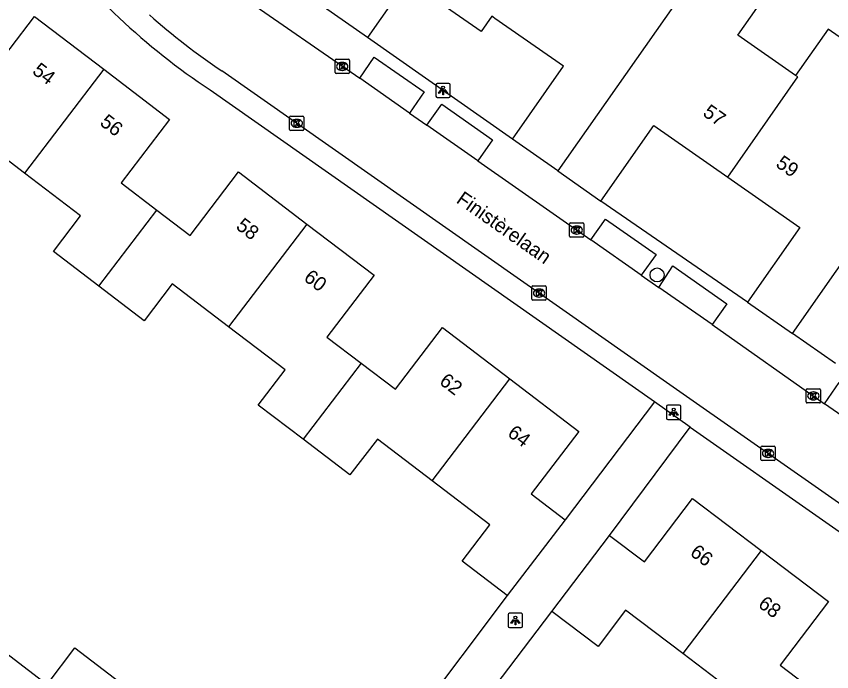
# Model space of a CAD drawing. Extents: x 158474 to 159560, y 388525 to 389605.
# Drawn here: x 158654.3 to 158711.4, y 389093.6 to 389139.5 of the extents above; entities that cross this region are included whole.
import ezdxf

# ---------------------------------------------------------------- set-up
doc = ezdxf.new("R2010")
doc.units = 0
for name, color, linetype in [('IMGEO_Boom', 7, 'Continuous'), ('IMGEO_Kolk', 7, 'Continuous'), ('IMGEO_Lichtpunt', 7, 'Continuous'), ('IMGEO_Openbare_ruimte_label', 7, 'Continuous'), ('IMGEO_Pand', 7, 'Continuous'), ('IMGEO_Pand_nummerreeks', 7, 'Continuous'), ('IMGEO_Rijbaan_lokaal_open', 7, 'Continuous'), ('IMGEO_Voetpad_open', 7, 'Continuous')]:
    doc.layers.add(name, color=color, linetype=linetype)

msp = doc.modelspace()

# ---------------------------------------------------------------- linework, layer by layer
at = {"layer": 'IMGEO_Boom'}
msp.add_circle((158699.155, 389121.384), 0.489, dxfattribs=at)
at = {"layer": 'IMGEO_Kolk'}
for p, q in [((158676.596, 389135.583), (158676.596, 389136.435)), ((158676.671, 389136.509), (158677.523, 389136.509)), ((158677.084, 389136.289), (158677.109, 389136.289)), ((158677.597, 389136.435), (158677.597, 389135.583)), ((158677.107, 389135.729), (158677.082, 389135.729)), ((158677.523, 389135.509), (158676.671, 389135.509)), ((158673.409, 389131.592), (158673.409, 389132.444)), ((158673.484, 389132.518), (158674.336, 389132.518)), ((158673.897, 389132.298), (158673.922, 389132.298)), ((158674.41, 389132.444), (158674.41, 389131.592)), ((158673.92, 389131.738), (158673.895, 389131.738)), ((158674.336, 389131.518), (158673.484, 389131.518)), ((158693.025, 389124.107), (158693.025, 389124.959)), ((158693.1, 389125.033), (158693.952, 389125.033)), ((158693.513, 389124.813), (158693.538, 389124.813)), ((158694.026, 389124.959), (158694.026, 389124.107)), ((158693.536, 389124.253), (158693.511, 389124.253)), ((158693.952, 389124.033), (158693.1, 389124.033)), ((158690.386, 389119.688), (158690.386, 389120.54)), ((158690.461, 389120.614), (158691.313, 389120.614)), ((158690.874, 389120.394), (158690.899, 389120.394)), ((158691.387, 389120.54), (158691.387, 389119.688)), ((158690.897, 389119.834), (158690.872, 389119.834)), ((158691.313, 389119.614), (158690.461, 389119.614)), ((158709.682, 389113.405), (158710.534, 389113.405)), ((158709.607, 389112.479), (158709.607, 389113.331)), ((158710.095, 389113.185), (158710.12, 389113.185)), ((158710.608, 389113.331), (158710.608, 389112.479)), ((158710.534, 389112.405), (158709.682, 389112.405)), ((158710.118, 389112.625), (158710.093, 389112.625)), ((158706.435, 389108.445), (158706.435, 389109.297)), ((158706.51, 389109.371), (158707.362, 389109.371)), ((158706.923, 389109.151), (158706.948, 389109.151)), ((158707.436, 389109.297), (158707.436, 389108.445)), ((158707.362, 389108.371), (158706.51, 389108.371)), ((158706.946, 389108.591), (158706.921, 389108.591))]:
    msp.add_line(p, q, dxfattribs=at)
for points in [[(158676.596, 389135.583), (158676.596, 389136.435)], [(158676.671, 389136.509), (158677.523, 389136.509)], [(158677.597, 389136.435), (158677.597, 389135.583)], [(158676.917, 389136.209), (158677.04, 389136.209), (158677.04, 389136.058), (158677.17, 389136.209), (158677.334, 389136.209), (158677.188, 389136.058), (158677.341, 389135.809), (158677.189, 389135.809), (158677.104, 389135.973), (158677.04, 389135.906), (158677.04, 389135.809), (158676.917, 389135.809), (158676.917, 389136.209)], [(158677.523, 389135.509), (158676.671, 389135.509)], [(158673.409, 389131.592), (158673.409, 389132.444)], [(158673.484, 389132.518), (158674.336, 389132.518)], [(158674.41, 389132.444), (158674.41, 389131.592)], [(158673.73, 389132.218), (158673.853, 389132.218), (158673.853, 389132.067), (158673.983, 389132.218), (158674.147, 389132.218), (158674.001, 389132.067), (158674.154, 389131.818), (158674.002, 389131.818), (158673.917, 389131.982), (158673.853, 389131.915), (158673.853, 389131.818), (158673.73, 389131.818), (158673.73, 389132.218)], [(158674.336, 389131.518), (158673.484, 389131.518)], [(158693.025, 389124.107), (158693.025, 389124.959)], [(158693.1, 389125.033), (158693.952, 389125.033)], [(158694.026, 389124.959), (158694.026, 389124.107)], [(158693.346, 389124.733), (158693.469, 389124.733), (158693.469, 389124.582), (158693.599, 389124.733), (158693.763, 389124.733), (158693.617, 389124.582), (158693.77, 389124.333), (158693.618, 389124.333), (158693.533, 389124.497), (158693.469, 389124.43), (158693.469, 389124.333), (158693.346, 389124.333), (158693.346, 389124.733)], [(158693.952, 389124.033), (158693.1, 389124.033)], [(158690.386, 389119.688), (158690.386, 389120.54)], [(158690.461, 389120.614), (158691.313, 389120.614)], [(158690.707, 389120.314), (158690.83, 389120.314), (158690.83, 389120.163), (158690.96, 389120.314), (158691.124, 389120.314), (158690.978, 389120.163), (158691.131, 389119.914), (158690.979, 389119.914), (158690.894, 389120.078), (158690.83, 389120.011), (158690.83, 389119.914), (158690.707, 389119.914), (158690.707, 389120.314)], [(158691.387, 389120.54), (158691.387, 389119.688)], [(158691.313, 389119.614), (158690.461, 389119.614)], [(158709.682, 389113.405), (158710.534, 389113.405)], [(158709.607, 389112.479), (158709.607, 389113.331)], [(158709.928, 389113.105), (158710.051, 389113.105), (158710.051, 389112.954), (158710.181, 389113.105), (158710.345, 389113.105), (158710.199, 389112.954), (158710.352, 389112.705), (158710.2, 389112.705), (158710.115, 389112.869), (158710.051, 389112.802), (158710.051, 389112.705), (158709.928, 389112.705), (158709.928, 389113.105)], [(158710.608, 389113.331), (158710.608, 389112.479)], [(158710.534, 389112.405), (158709.682, 389112.405)], [(158706.435, 389108.445), (158706.435, 389109.297)], [(158706.51, 389109.371), (158707.362, 389109.371)], [(158706.756, 389109.071), (158706.879, 389109.071), (158706.879, 389108.92), (158707.009, 389109.071), (158707.173, 389109.071), (158707.027, 389108.92), (158707.18, 389108.671), (158707.028, 389108.671), (158706.943, 389108.835), (158706.879, 389108.768), (158706.879, 389108.671), (158706.756, 389108.671), (158706.756, 389109.071)], [(158707.436, 389109.297), (158707.436, 389108.445)], [(158707.362, 389108.371), (158706.51, 389108.371)]]:
    msp.add_lwpolyline(points, dxfattribs=at)
for centre, start, end in [((158676.673, 389136.433), 91.552, 178.448), ((158676.673, 389136.433), 91.552, 178.448), ((158677.521, 389136.433), 1.552, 88.448), ((158677.521, 389136.433), 1.552, 88.448), ((158676.673, 389135.585), 181.552, 268.448), ((158676.673, 389135.585), 181.552, 268.448), ((158677.521, 389135.585), 271.552, 358.448), ((158677.521, 389135.585), 271.552, 358.448), ((158673.486, 389132.442), 91.552, 178.448), ((158673.486, 389132.442), 91.552, 178.448), ((158674.334, 389132.442), 1.552, 88.448), ((158674.334, 389132.442), 1.552, 88.448), ((158673.486, 389131.594), 181.552, 268.448), ((158673.486, 389131.594), 181.552, 268.448), ((158674.334, 389131.594), 271.552, 358.448), ((158674.334, 389131.594), 271.552, 358.448), ((158693.102, 389124.957), 91.552, 178.448), ((158693.102, 389124.957), 91.552, 178.448), ((158693.95, 389124.957), 1.552, 88.448), ((158693.95, 389124.957), 1.552, 88.448), ((158693.102, 389124.109), 181.552, 268.448), ((158693.102, 389124.109), 181.552, 268.448), ((158693.95, 389124.109), 271.552, 358.448), ((158693.95, 389124.109), 271.552, 358.448), ((158690.463, 389120.538), 91.552, 178.448), ((158690.463, 389120.538), 91.552, 178.448), ((158691.311, 389120.538), 1.552, 88.448), ((158691.311, 389120.538), 1.552, 88.448), ((158690.463, 389119.69), 181.552, 268.448), ((158690.463, 389119.69), 181.552, 268.448), ((158691.311, 389119.69), 271.552, 358.448), ((158691.311, 389119.69), 271.552, 358.448), ((158709.684, 389113.329), 91.552, 178.448), ((158709.684, 389113.329), 91.552, 178.448), ((158710.532, 389113.329), 1.552, 88.448), ((158710.532, 389113.329), 1.552, 88.448), ((158709.684, 389112.481), 181.552, 268.448), ((158709.684, 389112.481), 181.552, 268.448), ((158710.532, 389112.481), 271.552, 358.448), ((158710.532, 389112.481), 271.552, 358.448), ((158706.512, 389109.295), 91.552, 178.448), ((158706.512, 389109.295), 91.552, 178.448), ((158707.36, 389109.295), 1.552, 88.448), ((158707.36, 389109.295), 1.552, 88.448), ((158706.512, 389108.447), 181.552, 268.448), ((158706.512, 389108.447), 181.552, 268.448), ((158707.36, 389108.447), 271.552, 358.448), ((158707.36, 389108.447), 271.552, 358.448)]:
    msp.add_arc(centre, 0.0765, start, end, dxfattribs=at)
for centre, major_axis, ratio, start_param, end_param in [((158677.083, 389136.009), (-0.387, 0.002), 0.722429, 4.712389, 7.853982), ((158677.108, 389136.009), (-0.39, 0.002), 0.717154, 1.570796, 4.712389), ((158673.896, 389132.018), (-0.387, 0.002), 0.722429, 4.712389, 7.853982), ((158673.921, 389132.018), (-0.39, 0.002), 0.717154, 1.570796, 4.712389), ((158693.512, 389124.533), (-0.387, 0.002), 0.722429, 4.712389, 7.853982), ((158693.537, 389124.533), (-0.39, 0.002), 0.717154, 1.570796, 4.712389), ((158690.873, 389120.114), (-0.387, 0.002), 0.722429, 4.712389, 7.853982), ((158690.898, 389120.114), (-0.39, 0.002), 0.717154, 1.570796, 4.712389), ((158710.094, 389112.905), (-0.387, 0.002), 0.722429, 4.712389, 7.853982), ((158710.119, 389112.905), (-0.39, 0.002), 0.717154, 1.570796, 4.712389), ((158706.922, 389108.871), (-0.387, 0.002), 0.722429, 4.712389, 7.853982), ((158706.947, 389108.871), (-0.39, 0.002), 0.717154, 1.570796, 4.712389)]:
    msp.add_ellipse(centre, major_axis=major_axis, ratio=ratio, start_param=start_param, end_param=end_param, dxfattribs=at)
at = {"layer": 'IMGEO_Lichtpunt'}
for p, q in [((158683.662, 389134.725), (158683.662, 389133.918)), ((158683.662, 389134.725), (158683.662, 389133.918)), ((158684.564, 389134.82), (158683.756, 389134.82)), ((158684.564, 389134.82), (158683.756, 389134.82)), ((158684.658, 389133.918), (158684.658, 389134.725)), ((158684.658, 389133.918), (158684.658, 389134.725)), ((158683.756, 389133.824), (158684.564, 389133.824)), ((158683.756, 389133.824), (158684.564, 389133.824)), ((158700.726, 389112.25), (158699.918, 389112.25)), ((158700.726, 389112.25), (158699.918, 389112.25)), ((158699.824, 389112.155), (158699.824, 389111.348)), ((158699.824, 389112.155), (158699.824, 389111.348)), ((158700.82, 389111.348), (158700.82, 389112.155)), ((158700.82, 389111.348), (158700.82, 389112.155)), ((158699.918, 389111.254), (158700.726, 389111.254)), ((158699.918, 389111.254), (158700.726, 389111.254)), ((158688.727, 389097.561), (158688.727, 389096.754)), ((158688.727, 389097.561), (158688.727, 389096.754)), ((158689.629, 389097.656), (158688.821, 389097.656)), ((158689.629, 389097.656), (158688.821, 389097.656)), ((158689.723, 389096.754), (158689.723, 389097.561)), ((158689.723, 389096.754), (158689.723, 389097.561)), ((158688.821, 389096.66), (158689.629, 389096.66)), ((158688.821, 389096.66), (158689.629, 389096.66))]:
    msp.add_line(p, q, dxfattribs=at)
for points in [[(158684.036, 389134.389), (158684.075, 389134.361), (158683.887, 389134.099), (158683.849, 389134.126), (158684.036, 389134.389)], [(158684.138, 389134.341), (158684.185, 389134.341), (158684.185, 389134.019), (158684.138, 389134.019), (158684.138, 389134.341)], [(158684.248, 389134.361), (158684.286, 389134.388), (158684.473, 389134.126), (158684.434, 389134.098), (158684.248, 389134.361)], [(158700.198, 389111.819), (158700.237, 389111.791), (158700.049, 389111.529), (158700.011, 389111.556), (158700.198, 389111.819)], [(158700.3, 389111.771), (158700.347, 389111.771), (158700.347, 389111.449), (158700.3, 389111.449), (158700.3, 389111.771)], [(158700.41, 389111.791), (158700.448, 389111.818), (158700.635, 389111.556), (158700.596, 389111.528), (158700.41, 389111.791)], [(158689.101, 389097.225), (158689.14, 389097.197), (158688.952, 389096.935), (158688.914, 389096.962), (158689.101, 389097.225)], [(158689.203, 389097.177), (158689.25, 389097.177), (158689.25, 389096.855), (158689.203, 389096.855), (158689.203, 389097.177)], [(158689.313, 389097.197), (158689.351, 389097.224), (158689.538, 389096.962), (158689.499, 389096.934), (158689.313, 389097.197)]]:
    msp.add_lwpolyline(points, dxfattribs=at)
for centre in [(158684.161, 389134.523), (158700.323, 389111.953), (158689.226, 389097.359)]:
    msp.add_circle(centre, 0.0994, dxfattribs=at)
for centre, start, end in [((158683.756, 389134.725), 90, 180), ((158683.756, 389134.725), 90, 180), ((158684.564, 389134.725), 0, 90), ((158684.564, 389134.725), 0, 90), ((158683.756, 389133.918), 180, 270), ((158683.756, 389133.918), 180, 270), ((158684.564, 389133.918), 270, 0), ((158684.564, 389133.918), 270, 360), ((158699.918, 389112.155), 90, 180), ((158699.918, 389112.155), 90, 180), ((158700.726, 389112.155), 0, 90), ((158700.726, 389112.155), 0, 90), ((158699.918, 389111.348), 180, 270), ((158699.918, 389111.348), 180, 270), ((158700.726, 389111.348), 270, 0), ((158700.726, 389111.348), 270, 360), ((158688.821, 389097.561), 90, 180), ((158688.821, 389097.561), 90, 180), ((158689.629, 389097.561), 0, 90), ((158689.629, 389097.561), 0, 90), ((158688.821, 389096.754), 180, 270), ((158688.821, 389096.754), 180, 270), ((158689.629, 389096.754), 270, 0), ((158689.629, 389096.754), 270, 360)]:
    msp.add_arc(centre, 0.0946, start, end, dxfattribs=at)
at = {"layer": 'IMGEO_Pand'}
for points in [[(158706.6, 389149.21), (158692.205, 389128.68)], [(158708.866, 389135.374), (158704.825, 389138.201), (158710.579, 389146.426)], [(158678.87, 389138.048), (158672.706, 389142.361)], [(158687.572, 389139.529), (158686.821, 389138.453), (158681.673, 389142.055), (158678.87, 389138.048)], [(158719.812, 389141.67), (158715.538, 389135.561), (158711.148, 389138.632), (158708.866, 389135.374)], [(158654.833, 389128.524), (158650.765, 389131.627), (158648.887, 389129.165), (158645.71, 389131.588), (158646.678, 389132.857), (158649.71, 389136.832), (158652.092, 389135.016), (158655.527, 389139.519), (158660.391, 389135.809)], [(158689.021, 389130.907), (158692.594, 389136.016), (158687.793, 389139.374), (158687.673, 389139.458), (158687.572, 389139.529)], [(158708.635, 389117.286), (158723.78, 389138.91)], [(158660.391, 389135.809), (158654.833, 389128.524)], [(158660.391, 389135.809), (158664.997, 389132.295), (158661.599, 389127.84), (158664.107, 389125.927)], [(158704.114, 389128.252), (158709.017, 389135.269), (158708.866, 389135.374)], [(158695.221, 389126.57), (158698.933, 389131.877), (158704.114, 389128.252)], [(158692.205, 389128.68), (158689.021, 389130.907)], [(158660.036, 389120.591), (158656.852, 389123.02), (158658.764, 389125.526), (158654.833, 389128.524)], [(158664.107, 389125.927), (158666.433, 389124.152), (158669.833, 389128.609), (158674.62, 389124.957)], [(158692.205, 389128.68), (158695.221, 389126.57)], [(158704.114, 389128.252), (158709.162, 389124.721), (158705.497, 389119.481)], [(158660.036, 389120.591), (158664.107, 389125.927)], [(158674.62, 389124.957), (158669.124, 389117.753)], [(158674.62, 389124.957), (158679.33, 389121.365), (158676.023, 389117.031), (158678.428, 389115.197)], [(158669.124, 389117.753), (158665.184, 389120.758), (158663.21, 389118.17), (158660.036, 389120.591)], [(158705.497, 389119.481), (158708.635, 389117.286)], [(158674.355, 389109.86), (158671.208, 389112.261), (158673.09, 389114.728), (158669.124, 389117.753)], [(158678.428, 389115.197), (158680.826, 389113.367), (158684.126, 389117.692), (158688.842, 389114.094)], [(158711.658, 389115.172), (158708.635, 389117.286)], [(158678.428, 389115.197), (158674.355, 389109.86)], [(158683.39, 389106.949), (158688.842, 389114.094)], [(158688.842, 389114.094), (158693.667, 389110.414), (158690.325, 389106.033), (158692.708, 389104.215)], [(158683.39, 389106.949), (158679.556, 389109.874), (158677.637, 389107.357), (158674.355, 389109.86)], [(158688.657, 389098.904), (158685.492, 389101.318), (158687.434, 389103.864), (158683.39, 389106.949)], [(158695.827, 389103.12), (158698.265, 389101.272), (158701.633, 389105.715), (158706.446, 389102.066)], [(158692.708, 389104.215), (158688.657, 389098.904)], [(158691.779, 389097.78), (158695.827, 389103.12)], [(158706.446, 389102.066), (158700.955, 389094.828)], [(158706.446, 389102.066), (158711.171, 389098.484), (158707.79, 389094.023), (158710.218, 389092.182)], [(158700.955, 389094.828), (158696.945, 389097.868), (158695.017, 389095.325), (158691.779, 389097.78)], [(158652.463, 389095.674), (158656.42, 389092.671), (158658.359, 389095.225), (158661.535, 389092.814)], [(158706.182, 389086.862), (158702.948, 389089.314), (158704.875, 389091.856), (158700.955, 389094.828)]]:
    msp.add_lwpolyline(points, dxfattribs=at)
at = {"layer": 'IMGEO_Rijbaan_lokaal_open'}
for points in [[(158668.417, 389142.153), (158670.083, 389140.909), (158678.316, 389135.175)], [(158712.105, 389105.251), (158700.051, 389113.689), (158668.668, 389135.691)], [(158681.802, 389132.741), (158678.316, 389135.175)], [(158698.976, 389112.491), (158667.837, 389134.355)], [(158681.802, 389132.741), (158683.027, 389131.885)], [(158686.589, 389129.391), (158683.027, 389131.885)], [(158686.589, 389129.391), (158694.513, 389123.837)], [(158698.044, 389121.368), (158694.513, 389123.837)], [(158698.044, 389121.368), (158699.282, 389120.506)], [(158703.009, 389117.912), (158699.282, 389120.506)], [(158703.009, 389117.912), (158710.878, 389112.337)], [(158698.976, 389112.491), (158692.708, 389104.215)], [(158701.475, 389110.704), (158698.976, 389112.491)], [(158714.59, 389109.772), (158710.878, 389112.337)], [(158695.827, 389103.12), (158701.475, 389110.704)], [(158701.475, 389110.704), (158720.018, 389097.701)], [(158688.657, 389098.904), (158682.238, 389090.356)], [(158678.338, 389080.036), (158691.779, 389097.78)]]:
    msp.add_lwpolyline(points, dxfattribs=at)
for centre, radius, start, end in [((158695.238, 389175.428), 49.374, 217.4119, 236.2911), ((158694.372, 389174.125), 46.237, 228.2662, 236.2265)]:
    msp.add_arc(centre, radius, start, end, dxfattribs=at)
at = {"layer": 'IMGEO_Voetpad_open'}
for points in [[(158689.021, 389130.907), (158678.87, 389138.048)], [(158678.316, 389135.175), (158679.337, 389136.657), (158682.838, 389134.223), (158681.802, 389132.741)], [(158683.027, 389131.885), (158684.068, 389133.353), (158687.626, 389130.849), (158686.589, 389129.391)], [(158705.497, 389119.481), (158695.221, 389126.57)], [(158694.513, 389123.837), (158695.539, 389125.304), (158699.087, 389122.82), (158698.044, 389121.368)], [(158699.282, 389120.506), (158700.258, 389122.013), (158704.038, 389119.361), (158703.009, 389117.912)], [(158710.878, 389112.337), (158711.904, 389113.831), (158715.578, 389111.196), (158714.59, 389109.772)]]:
    msp.add_lwpolyline(points, dxfattribs=at)

# ---------------------------------------------------------------- texts
at = {"layer": 'IMGEO_Openbare_ruimte_label'}
msp.add_text('Finistèrelaan', height=1, rotation=324.8953, dxfattribs=at).set_placement((158685.019, 389126.502))
at = {"layer": 'IMGEO_Pand_nummerreeks'}
for s, rotation, p in [('54', 322.6524, (158655.312, 389135.557)), ('57', 325.0209, (158702.291, 389132.603)), ('56', 322.6732, (158660.048, 389131.944)), ('59', 325.0267, (158707.405, 389129.025)), ('58', 322.6648, (158669.583, 389124.674)), ('60', 322.6648, (158674.331, 389121.052)), ('62', 322.6452, (158683.834, 389113.788)), ('64', 322.6807, (158688.609, 389110.146)), ('66', 322.8333, (158701.399, 389101.776)), ('68', 322.8333, (158706.17, 389098.158))]:
    msp.add_text(s, height=1, rotation=rotation, dxfattribs=at).set_placement(p)

doc.saveas('drawing.dxf')
